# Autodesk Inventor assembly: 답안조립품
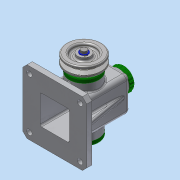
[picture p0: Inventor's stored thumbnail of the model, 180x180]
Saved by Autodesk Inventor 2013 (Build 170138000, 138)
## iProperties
Created: 2018-10
Part Number: 답안조립품
Document SubType Name: Assembly
Designer: Administrator
Author: Administrator
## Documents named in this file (14)
- C:\Users\Administrator\Desktop\481013V1004\답안조립품.iam
- C:\Users\Administrator\Desktop\481013V1004\본체.ipt
- C:\Users\Administrator\Desktop\481013V1004\V-벨트풀리.ipt
- C:\Users\Administrator\Desktop\481013V1004\뒤커버.ipt
- C:\Users\Administrator\Desktop\481013V1004\멈춤링 15 x 1.ipt
- C:\Users\Administrator\Desktop\481013V1004\베어링 15 x 35 x 11.ipt
- C:\Users\Administrator\Desktop\481013V1004\볼트 M4 x 10.ipt
- C:\Users\Administrator\Desktop\481013V1004\볼트 M6 x 12.ipt
- C:\Users\Administrator\Desktop\481013V1004\상부캡.ipt
- C:\Users\Administrator\Desktop\481013V1004\앞커버.ipt
- C:\Users\Administrator\Desktop\481013V1004\오일실 15 25 7.ipt
- C:\Users\Administrator\Desktop\481013V1004\와셔.ipt
- C:\Users\Administrator\Desktop\481013V1004\축.ipt
- C:\Users\Administrator\Desktop\481013V1004\키 5 x 5 x 14.ipt
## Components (1 placed, 1 different names)
1. V-벨트풀리:1
